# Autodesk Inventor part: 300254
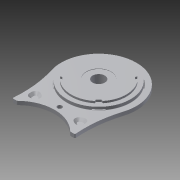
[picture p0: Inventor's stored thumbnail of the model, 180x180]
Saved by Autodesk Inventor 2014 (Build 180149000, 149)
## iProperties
Created: 2007-11
Part Number: 300254
Document SubType Name: Modeling
Designer: TH
Density: 7.85 g/cm^3
Mass: 336.369 g
Surface Area: 156.51 cm^2
Volume: 42.8495 cm^3
Material: Steel
Description: BACK PIVOT PLATE
Appearance: Aluminum - Flat
Component Category: Back Component
Author: TH
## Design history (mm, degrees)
sketch "Sketch1"
  geometry: L1 (0, 67)-(0, -115) reference; L2 (-29.394, -60)-(-33, -60); L3 (33, -60)-(29.394, -60); A1 r 41 centre (0, 0) between (39.174, -12.101) and (-39.174, -12.101); A2 r 1 centre (-33, -59) between (-33.997, -58.921) and (-33, -60); A3 r 1 centre (33, -59) between (33, -60) and (33.997, -58.921); A4 r 125.042 centre (-158.645, -49.007) between (-33.997, -58.921) and (-39.174, -12.101); A5 r 125.042 centre (158.645, -49.007) between (39.174, -12.101) and (33.997, -58.921); A6 r 41 centre (0, -89) between (28.694, -59.714) and (-28.694, -59.714); A7 r 1 centre (29.394, -59) between (28.694, -59.714) and (29.394, -60); A8 r 1 centre (-29.394, -59) between (-29.394, -60) and (-28.694, -59.714); 1 further point
  constraints: 17 point on circle, 9 tangent, 8 centre point, 4 end point, 3 symmetric about line, 1 coincident, 1 collinear, 1 equal radius, 1 perpendicular, 1 point on line, 1 other
  dimensions: "d0" = 2 diameter of A2; "d2" = 82 diameter of A1; "d3" = 59 vertical distance of A2.centre point (0, 0); "d5" = 33 horizontal distance of A2.centre point (0, 0); "d8" = 317.29074 distance of A5.centre A4.centre; "d46" = 1 radius of A3; "d47" = 82 diameter of A6; "d48" = 89 distance of point (0, 0) A6.centre; "d49" = 1 radius of A7
extrude "Extrusion1" new body sketch "Sketch1" distance "d11" = 4; taper "d12" = 0 deg
sketch "Sketch2"
  geometry: L1 (0, -117.105)-(0, 67.351) reference; L2 (33, -60)-(29.394, -60) reference; L3 (-22, -42.585)-(-23.95, -41.459); L4 (-27.7, -43.624)-(-27.7, -45.876); L5 (-23.95, -48.041)-(-22, -46.915); A1 r 41 centre (0, 0) between (39.174, -12.101) and (-39.174, -12.101) reference; A2 r 1 centre (-33, -59) between (-33.997, -58.921) and (-33, -60) reference; A3 r 2.5 centre (-25.2, -43.624) between (-23.95, -41.459) and (-27.7, -43.624); A4 r 2.5 centre (-25.2, -45.876) between (-27.7, -45.876) and (-23.95, -48.041); A5 r 2.5 centre (-23.25, -44.75) between (-22, -46.915) and (-22, -42.585); 3 further points
  constraints: 8 point on circle, 6 end point, 6 tangent, 3 centre point, 2 equal radius, 1 perpendicular
  dimensions: "d15" = 2.5 radius of A3; "d16" = 23.25 horizontal distance of A1.centre A5.centre; "d17" = 44.75 vertical distance of A1.centre A5.centre; "d19" = 1.95 horizontal distance of A3.centre A5.centre; "d50" = 60 deg angle of L1 L5; "d51" = 60 deg angle of L5 L3
extrude "Extrusion2" join sketch "Sketch2" distance "d20" = 2.5; taper "d21" = 0 deg
chamfer "Chamfer1" distance "d22" = 2.5; stored, may be unused: second distance "d23" = 2, angle "d24" = 45 deg
mirror "Mirror1"
sketch "Sketch3"
  geometry: L1 (-23.075, -49.556)-(-21.125, -48.431); L2 (-21.125, -41.069)-(-23.075, -39.944); L3 (-29.45, -43.624)-(-29.45, -45.876); L4 (-23.95, -41.459)-(-22, -42.585) reference; L5 (-22, -46.915)-(-23.95, -48.041) reference; L6 (-27.7, -45.876)-(-27.7, -43.624) reference; A1 r 2.5 centre (-23.25, -44.75) between (-22, -46.915) and (-22, -42.585) reference; A2 r 2.5 centre (-25.2, -45.876) between (-27.7, -45.876) and (-23.95, -48.041) reference; A3 r 2.5 centre (-25.2, -43.624) between (-23.95, -41.459) and (-27.7, -43.624) reference; A4 r 4.25 centre (-23.25, -44.75) between (-21.125, -48.431) and (-21.125, -41.069); A5 r 4.25 centre (-25.2, -43.624) between (-23.075, -39.944) and (-29.45, -43.624); A6 r 4.25 centre (-25.2, -45.876) between (-29.45, -45.876) and (-23.075, -49.556)
  constraints: 6 end point, 6 point on circle, 3 centre point
extrude "Extrusion3" cut sketch "Sketch3" distance "d25" = 2.5; taper "d26" = 0 deg
chamfer "Chamfer2" distance "d27" = 2.5; stored, may be unused: second distance "d28" = 2, angle "d29" = 45 deg
mirror "Mirror2"
sketch "Sketch4"
  geometry: L1 (0, 0)-(0, -42.5); C1 r 6.7 at (0, 0); C2 r 2.5 at (0, -42.5); 1 further point
  constraints: 2 centre point, 2 coincident, 2 end point, 1 vertical
  dimensions: "d31" = 13.4 diameter of C1; "d32" = 42.5 distance of L1.start L1.end; "d33" = 5 diameter of C2
extrude "Extrusion4" cut sketch "Sketch4" stored distance "d34" = 2.5; taper "d35" = 0 deg
sketch "Sketch6"
  geometry: L1 (6.7, -4)-(6.7, 0) reference; L2 (6.7, 0)-(41, 0) reference; L3 (41, 0)-(41, -4) reference; L4 (41, -4)-(6.7, -4) reference; L5 (-6.7, 0)-(-6.7, -4) reference; L6 (-6.7, -4)-(-41, -4) reference; L7 (-41, -4)-(-41, 0) reference; L8 (-41, 0)-(-6.7, 0) reference; L9 (-34.665, 0)-(-34.665, 3.3); L10 (-34.665, 3.3)-(-30, 3.3); L11 (-30, 3.3)-(-30, 5.4); L12 (-30, 5.4)-(-13.5, 5.4); L13 (-13.5, 5.4)-(-13.5, 5); L14 (-13.5, 5)-(-6.7, 5); L15 (-6.7, 5)-(-6.7, 0); L16 (6.7, -4)-(6.7, 0) reference; L17 (6.7, 0)-(41, 0) reference; L18 (41, 0)-(41, -4) reference; L19 (41, -4)-(6.7, -4) reference; L20 (-6.7, 0)-(-6.7, -4) reference; L21 (-6.7, -4)-(-41, -4) reference; L22 (-41, -4)-(-41, 0) reference; L23 (-41, 0)-(-6.7, 0) reference; L24 (6.7, -4)-(6.7, 0) reference; L25 (6.7, 0)-(41, 0) reference; L26 (41, 0)-(41, -4) reference; L27 (41, -4)-(6.7, -4) reference; L28 (-6.7, 0)-(-6.7, -4) reference; L29 (-6.7, -4)-(-41, -4) reference; L30 (-41, -4)-(-41, 0) reference; L31 (-41, 0)-(-6.7, 0) reference; L32 (6.7, -4)-(6.7, 0) reference; L33 (6.7, 0)-(41, 0) reference; L34 (41, 0)-(41, -4) reference; L35 (41, -4)-(6.7, -4) reference; L36 (-6.7, 0)-(-6.7, -4) reference; L37 (-6.7, -4)-(-41, -4) reference; L38 (-41, -4)-(-41, 0) reference; L39 (-41, 0)-(-6.7, 0) reference; L40 (6.7, -4)-(6.7, 0) reference; L41 (6.7, 0)-(41, 0) reference; L42 (41, 0)-(41, -4) reference; L43 (41, -4)-(6.7, -4) reference; L44 (-6.7, 0)-(-6.7, -4) reference; L45 (-6.7, -4)-(-41, -4) reference; L46 (-41, -4)-(-41, 0) reference; L47 (-41, 0)-(-6.7, 0) reference; L48 (6.7, -4)-(6.7, 0) reference; L49 (6.7, 0)-(41, 0) reference; L50 (41, 0)-(41, -4) reference; L51 (41, -4)-(6.7, -4) reference; L52 (-6.7, 0)-(-6.7, -4) reference; L53 (-6.7, -4)-(-41, -4) reference; L54 (-41, -4)-(-41, 0) reference; L55 (-41, 0)-(-6.7, 0) reference; L56 (0, -8.88)-(0, 7.78) reference; 1 further point
  constraints: 14 end point, 6 parallel, 2 perpendicular, 1 point on line
  dimensions: "d52" = 5 distance of L14.end L5.start; "d53" = 5.4 distance between parallel lines of L8 L12; "d54" = 3.3 distance between parallel lines of L8 L10; "d55" = 34.665 distance from line of point (0, 0) L9; "d56" = 30 distance from line of point (0, 0) L11; "d57" = 13.5 distance from line of point (0, 0) L13
revolve "Revolution1" sketch "Sketch6" stored, may be unused: angle "d58" = 90 deg
workplane "Work Plane1"
sketch "Sketch7"
  geometry: L1 (3.3, -34.665)-(0, -34.665) reference; L2 (0, -34.665)-(0, -41) reference; L3 (0, -41)-(-4, -41) reference; L4 (-4, -41)-(-4, -6.7) reference; L5 (-4, -6.7)-(5, -6.7) reference; L6 (5, -6.7)-(5, -13.5) reference; L7 (5, -13.5)-(5.4, -13.5) reference; L8 (5.4, -13.5)-(5.4, -30) reference; L9 (5.4, -30)-(3.3, -30) reference; L10 (3.3, -30)-(3.3, -34.665) reference; L11 (0, 34.665)-(3.3, 34.665) reference; L12 (3.3, 34.665)-(3.3, 30) reference; L13 (3.3, 30)-(5.4, 30) reference; L14 (5.4, 30)-(5.4, 13.5) reference; L15 (5.4, 13.5)-(5, 13.5) reference; L16 (5, 13.5)-(5, 6.7) reference; L17 (5, 6.7)-(-4, 6.7) reference; L18 (-4, 6.7)-(-4, 48.724) reference; L19 (-4, 48.724)-(0, 48.724) reference; L20 (0, 48.724)-(0, 34.665) reference; L21 (0, 35.665)-(1, 34.665); L22 (3.3, -34.665)-(0, -34.665) reference; L23 (0, -34.665)-(0, -41) reference; L24 (0, -41)-(-4, -41) reference; L25 (-4, -41)-(-4, -6.7) reference; L26 (-4, -6.7)-(5, -6.7) reference; L27 (5, -6.7)-(5, -13.5) reference; L28 (5, -13.5)-(5.4, -13.5) reference; L29 (5.4, -13.5)-(5.4, -30) reference; L30 (5.4, -30)-(3.3, -30) reference; L31 (3.3, -30)-(3.3, -34.665) reference; L32 (0, 34.665)-(3.3, 34.665) reference; L33 (3.3, 34.665)-(3.3, 30) reference; L34 (3.3, 30)-(5.4, 30) reference; L35 (5.4, 30)-(5.4, 13.5) reference; L36 (5.4, 13.5)-(5, 13.5) reference; L37 (5, 13.5)-(5, 6.7) reference; L38 (5, 6.7)-(-4, 6.7) reference; L39 (-4, 6.7)-(-4, 48.724) reference; L40 (-4, 48.724)-(0, 48.724) reference; L41 (0, 48.724)-(0, 34.665) reference; L42 (3.3, -34.665)-(0, -34.665) reference; L43 (0, -34.665)-(0, -41) reference; L44 (0, -41)-(-4, -41) reference; L45 (-4, -41)-(-4, -6.7) reference; L46 (-4, -6.7)-(5, -6.7) reference; L47 (5, -6.7)-(5, -13.5) reference; L48 (5, -13.5)-(5.4, -13.5) reference; L49 (5.4, -13.5)-(5.4, -30) reference; L50 (5.4, -30)-(3.3, -30) reference; L51 (3.3, -30)-(3.3, -34.665) reference; L52 (0, 34.665)-(3.3, 34.665) reference; L53 (3.3, 34.665)-(3.3, 30) reference; L54 (3.3, 30)-(5.4, 30) reference; L55 (5.4, 30)-(5.4, 13.5) reference; L56 (5.4, 13.5)-(5, 13.5) reference; L57 (5, 13.5)-(5, 6.7) reference; L58 (5, 6.7)-(-4, 6.7) reference; L59 (-4, 6.7)-(-4, 48.724) reference; L60 (-4, 48.724)-(0, 48.724) reference; L61 (0, 48.724)-(0, 34.665) reference; L62 (-8.88, 0)-(7.78, 0) reference; 1 further point
  constraints: 2 end point, 2 point on line
  dimensions: "d60" = 35.665 distance of L21.start point (0, 0); "d61" = 45 deg angle of L20 L21
revolve "Revolution2" sketch "Sketch7" stored, may be unused: angle "d62" = 17.5 deg
pattern_circular "Circular Pattern2" dims angle "d64" = 360 deg
sketch "Sketch8"
  geometry: L1 (0, 0)-(21.213, -21.213); L2 (0, 61.2)-(0, -80.2) reference; L3 (17.99, -21.456)-(19.276, -22.988); L4 (21.456, -17.99)-(22.988, -19.276); A1 r 30 centre (0, 0) between (22.988, -19.276) and (19.276, -22.988) reference; A2 r 28 centre (0, 0) between (17.99, -21.456) and (21.456, -17.99); A3 r 28 centre (0, 0) between (0, 28) and (0, -28); 1 further point
  constraints: 8 point on circle, 6 end point, 3 point on line, 2 centre point, 1 coincident
  dimensions: "d66" = 45 deg angle of L2 L1; "d70" = 10 deg angle of L4 L3; "d71" = 5 deg angle of L1 L4; "d72" = 28 radius of A2; "d73" = 5.25 distance of L4.end L3.end
extrude "Extrusion6" cut sketch "Sketch8" stored distance "d74" = 10; taper "d75" = 0 deg
fillet "Fillet2" dims "d76" = 0.95
pattern_circular "Circular Pattern3" dims angle "d78" = 360 deg
fillet "Fillet3" dims "d80" = 0.25
body "Solid1"
node "Projected Loop1"
node "Project Cut Edges1"
node "Project Cut Edges2"
node "Project Cut Edges3"
node "Project Cut Edges4"
node "Project Cut Edges5"
node "Project Cut Edges6"
node "Project Cut Edges7"
node "Project Cut Edges8"
node "Project Cut Edges9"
other parameters: "d59" = 45 deg, "d67" = 5 deg, "d68" = 5 deg (= d67), "d69" = 56
